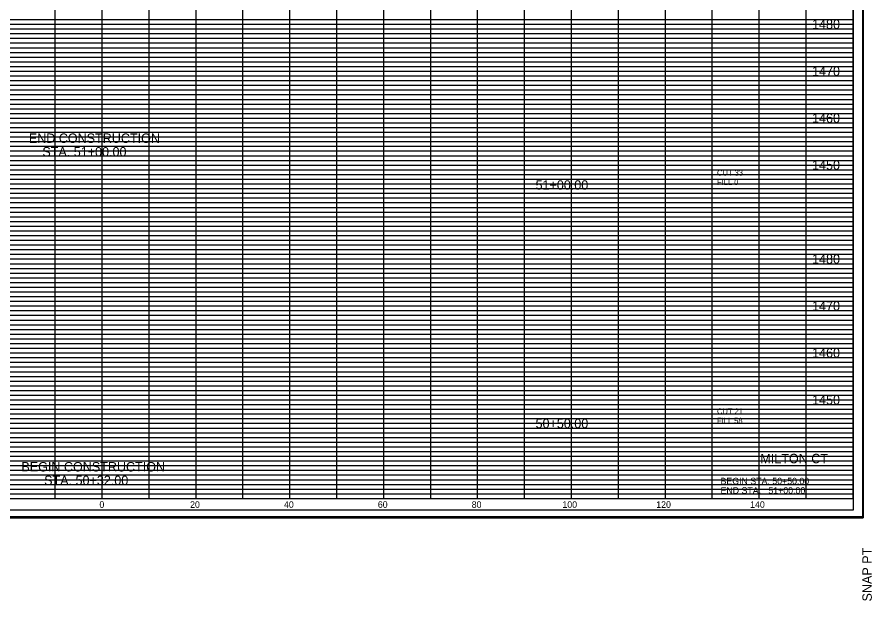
# Model space of a CAD drawing. Extents: x 980 to 1324, y 978 to 1227.
# Drawn here: x 1141.9 to 1324, y 978.2 to 1102.5 of the extents above; entities that cross this region are included whole.
import ezdxf

# ---------------------------------------------------------------- set-up
doc = ezdxf.new("R2010")
doc.units = 0
for name, color, linetype in [('DESIGN - SHEET - Corner Text', 7, 'Continuous'), ('DESIGN - SHEET - Light Grid', 7, 'Continuous'), ('DESIGN - SHEET - Linework', 7, 'Continuous'), ('DESIGN - SHEET - Plot Shape', 7, 'Continuous'), ('DESIGN - TYPICAL - Finished Grade and Subgrade', 7, 'Continuous'), ('DESIGN - TYPICAL - Text', 7, 'Continuous')]:
    doc.layers.add(name, color=color, linetype=linetype)

# ---------------------------------------------------------------- blocks, each defined once
blk = doc.blocks.new('XSTSHT')
at = {"layer": 'DESIGN - SHEET - Light Grid'}
for p, q in [((8, 10.2), (16, 10.2)), ((16, 10.2), (24, 10.2)), ((24, 10.2), (32, 10.2)), ((8, 10.1), (16, 10.1)), ((16, 10.1), (24, 10.1)), ((24, 10.1), (32, 10.1)), ((8, 9.9), (16, 9.9)), ((16, 9.9), (24, 9.9)), ((24, 9.9), (32, 9.9)), ((8, 9.8), (16, 9.8)), ((8, 9.7), (16, 9.7)), ((16, 9.8), (24, 9.8)), ((16, 9.7), (24, 9.7)), ((24, 9.8), (32, 9.8)), ((24, 9.7), (32, 9.7)), ((8, 9.6), (16, 9.6)), ((8, 9.5), (16, 9.5)), ((16, 9.6), (24, 9.6)), ((16, 9.5), (24, 9.5)), ((24, 9.6), (32, 9.6)), ((24, 9.5), (32, 9.5)), ((8, 9.4), (16, 9.4)), ((8, 9.3), (16, 9.3)), ((16, 9.4), (24, 9.4)), ((16, 9.3), (24, 9.3)), ((24, 9.4), (32, 9.4)), ((24, 9.3), (32, 9.3)), ((8, 9.2), (16, 9.2)), ((16, 9.2), (24, 9.2)), ((24, 9.2), (32, 9.2)), ((8, 9.1), (16, 9.1)), ((16, 9.1), (24, 9.1)), ((24, 9.1), (32, 9.1)), ((8, 8.9), (16, 8.9)), ((8, 8.8), (16, 8.8)), ((16, 8.9), (24, 8.9)), ((16, 8.8), (24, 8.8)), ((24, 8.9), (32, 8.9)), ((24, 8.8), (32, 8.8)), ((8, 8.7), (16, 8.7)), ((8, 8.6), (16, 8.6)), ((16, 8.7), (24, 8.7)), ((16, 8.6), (24, 8.6)), ((24, 8.7), (32, 8.7)), ((24, 8.6), (32, 8.6)), ((8, 8.5), (16, 8.5)), ((8, 8.4), (16, 8.4)), ((16, 8.5), (24, 8.5)), ((16, 8.4), (24, 8.4)), ((24, 8.5), (32, 8.5)), ((24, 8.4), (32, 8.4)), ((8, 8.3), (16, 8.3)), ((8, 8.2), (16, 8.2)), ((16, 8.3), (24, 8.3)), ((16, 8.2), (24, 8.2)), ((24, 8.3), (32, 8.3)), ((24, 8.2), (32, 8.2)), ((8, 8.1), (16, 8.1)), ((16, 8.1), (24, 8.1)), ((24, 8.1), (32, 8.1)), ((8, 7.9), (16, 7.9)), ((16, 7.9), (24, 7.9)), ((24, 7.9), (32, 7.9)), ((8, 7.8), (16, 7.8)), ((8, 7.7), (16, 7.7)), ((16, 7.8), (24, 7.8)), ((16, 7.7), (24, 7.7)), ((24, 7.8), (32, 7.8)), ((24, 7.7), (32, 7.7)), ((8, 7.6), (16, 7.6)), ((8, 7.5), (16, 7.5)), ((16, 7.6), (24, 7.6)), ((16, 7.5), (24, 7.5)), ((24, 7.6), (32, 7.6)), ((24, 7.5), (32, 7.5)), ((8, 7.4), (16, 7.4)), ((8, 7.3), (16, 7.3)), ((16, 7.4), (24, 7.4)), ((16, 7.3), (24, 7.3)), ((24, 7.4), (32, 7.4)), ((24, 7.3), (32, 7.3)), ((8, 7.2), (16, 7.2)), ((16, 7.2), (24, 7.2)), ((24, 7.2), (32, 7.2)), ((8, 7.1), (16, 7.1)), ((16, 7.1), (24, 7.1)), ((24, 7.1), (32, 7.1)), ((8, 6.9), (16, 6.9)), ((8, 6.8), (16, 6.8)), ((16, 6.9), (24, 6.9)), ((16, 6.8), (24, 6.8)), ((24, 6.9), (32, 6.9)), ((24, 6.8), (32, 6.8)), ((8, 6.7), (16, 6.7)), ((8, 6.6), (16, 6.6)), ((16, 6.7), (24, 6.7)), ((16, 6.6), (24, 6.6)), ((24, 6.7), (32, 6.7)), ((24, 6.6), (32, 6.6)), ((8, 6.5), (16, 6.5)), ((8, 6.4), (16, 6.4)), ((16, 6.5), (24, 6.5)), ((16, 6.4), (24, 6.4)), ((24, 6.5), (32, 6.5)), ((24, 6.4), (32, 6.4)), ((8, 6.3), (16, 6.3)), ((8, 6.2), (16, 6.2)), ((16, 6.3), (24, 6.3)), ((16, 6.2), (24, 6.2)), ((24, 6.3), (32, 6.3)), ((24, 6.2), (32, 6.2)), ((8, 6.1), (16, 6.1)), ((16, 6.1), (24, 6.1)), ((24, 6.1), (32, 6.1)), ((8, 5.9), (16, 5.9)), ((16, 5.9), (24, 5.9)), ((24, 5.9), (32, 5.9)), ((8, 5.8), (16, 5.8)), ((8, 5.7), (16, 5.7)), ((16, 5.8), (24, 5.8)), ((16, 5.7), (24, 5.7)), ((24, 5.8), (32, 5.8)), ((24, 5.7), (32, 5.7)), ((8, 5.6), (16, 5.6)), ((8, 5.5), (16, 5.5)), ((16, 5.6), (24, 5.6)), ((16, 5.5), (24, 5.5)), ((24, 5.6), (32, 5.6)), ((24, 5.5), (32, 5.5)), ((8, 5.4), (16, 5.4)), ((8, 5.3), (16, 5.3)), ((16, 5.4), (24, 5.4)), ((16, 5.3), (24, 5.3)), ((24, 5.4), (32, 5.4)), ((24, 5.3), (32, 5.3)), ((8, 5.2), (16, 5.2)), ((8, 5.1), (16, 5.1)), ((16, 5.2), (24, 5.2)), ((16, 5.1), (24, 5.1)), ((24, 5.2), (32, 5.2)), ((24, 5.1), (32, 5.1)), ((8, 4.9), (16, 4.9)), ((8, 4.8), (16, 4.8)), ((16, 4.9), (24, 4.9)), ((16, 4.8), (24, 4.8)), ((24, 4.9), (32, 4.9)), ((24, 4.8), (32, 4.8)), ((8, 4.7), (16, 4.7)), ((8, 4.6), (16, 4.6)), ((16, 4.7), (24, 4.7)), ((16, 4.6), (24, 4.6)), ((24, 4.7), (32, 4.7)), ((24, 4.6), (32, 4.6)), ((8, 4.5), (16, 4.5)), ((8, 4.4), (16, 4.4)), ((16, 4.5), (24, 4.5)), ((16, 4.4), (24, 4.4)), ((24, 4.5), (32, 4.5)), ((24, 4.4), (32, 4.4)), ((8, 4.3), (16, 4.3)), ((8, 4.2), (16, 4.2)), ((16, 4.3), (24, 4.3)), ((16, 4.2), (24, 4.2)), ((24, 4.3), (32, 4.3)), ((24, 4.2), (32, 4.2)), ((8, 4.1), (16, 4.1)), ((16, 4.1), (24, 4.1)), ((24, 4.1), (32, 4.1)), ((8, 3.9), (16, 3.9)), ((16, 3.9), (24, 3.9)), ((24, 3.9), (32, 3.9)), ((8, 3.8), (16, 3.8)), ((8, 3.7), (16, 3.7)), ((16, 3.8), (24, 3.8)), ((16, 3.7), (24, 3.7)), ((24, 3.8), (32, 3.8)), ((24, 3.7), (32, 3.7)), ((8, 3.6), (16, 3.6)), ((8, 3.5), (16, 3.5)), ((16, 3.6), (24, 3.6)), ((16, 3.5), (24, 3.5)), ((24, 3.6), (32, 3.6)), ((24, 3.5), (32, 3.5)), ((8, 3.4), (16, 3.4)), ((8, 3.3), (16, 3.3)), ((16, 3.4), (24, 3.4)), ((16, 3.3), (24, 3.3)), ((24, 3.4), (32, 3.4)), ((24, 3.3), (32, 3.3)), ((8, 3.2), (16, 3.2)), ((8, 3.1), (16, 3.1)), ((16, 3.2), (24, 3.2)), ((16, 3.1), (24, 3.1)), ((24, 3.2), (32, 3.2)), ((24, 3.1), (32, 3.1)), ((8, 2.9), (16, 2.9)), ((8, 2.8), (16, 2.8)), ((16, 2.9), (24, 2.9)), ((16, 2.8), (24, 2.8)), ((24, 2.9), (32, 2.9)), ((24, 2.8), (32, 2.8)), ((8, 2.7), (16, 2.7)), ((8, 2.6), (16, 2.6)), ((16, 2.7), (24, 2.7)), ((16, 2.6), (24, 2.6)), ((24, 2.7), (32, 2.7)), ((24, 2.6), (32, 2.6)), ((8, 2.5), (16, 2.5)), ((8, 2.4), (16, 2.4)), ((16, 2.5), (24, 2.5)), ((16, 2.4), (24, 2.4)), ((24, 2.5), (32, 2.5)), ((24, 2.4), (32, 2.4)), ((8, 2.3), (16, 2.3)), ((8, 2.2), (16, 2.2)), ((16, 2.3), (24, 2.3)), ((16, 2.2), (24, 2.2)), ((24, 2.3), (32, 2.3)), ((24, 2.2), (32, 2.2)), ((8, 2.1), (16, 2.1)), ((16, 2.1), (24, 2.1)), ((24, 2.1), (32, 2.1)), ((8, 1.9), (16, 1.9)), ((16, 1.9), (24, 1.9)), ((24, 1.9), (32, 1.9)), ((8, 1.8), (16, 1.8)), ((8, 1.7), (16, 1.7)), ((16, 1.8), (24, 1.8)), ((16, 1.7), (24, 1.7)), ((24, 1.8), (32, 1.8)), ((24, 1.7), (32, 1.7)), ((8, 1.6), (16, 1.6)), ((8, 1.5), (16, 1.5)), ((16, 1.6), (24, 1.6)), ((16, 1.5), (24, 1.5)), ((24, 1.6), (32, 1.6)), ((24, 1.5), (32, 1.5)), ((8, 1.4), (16, 1.4)), ((8, 1.3), (16, 1.3)), ((16, 1.4), (24, 1.4)), ((16, 1.3), (24, 1.3)), ((24, 1.4), (32, 1.4)), ((24, 1.3), (32, 1.3)), ((8, 1.2), (16, 1.2)), ((8, 1.1), (16, 1.1)), ((16, 1.2), (24, 1.2)), ((16, 1.1), (24, 1.1)), ((24, 1.2), (32, 1.2)), ((24, 1.1), (32, 1.1)), ((8, 0.9), (16, 0.9)), ((8, 0.8), (16, 0.8)), ((16, 0.9), (24, 0.9)), ((16, 0.8), (24, 0.8)), ((24, 0.9), (32, 0.9)), ((24, 0.8), (32, 0.8)), ((8, 0.7), (16, 0.7)), ((8, 0.6), (16, 0.6)), ((16, 0.7), (24, 0.7)), ((16, 0.6), (24, 0.6)), ((24, 0.7), (32, 0.7)), ((24, 0.6), (32, 0.6)), ((8, 0.5), (16, 0.5)), ((8, 0.4), (16, 0.4)), ((16, 0.5), (24, 0.5)), ((16, 0.4), (24, 0.4)), ((24, 0.5), (32, 0.5)), ((24, 0.4), (32, 0.4)), ((8, 0.3), (16, 0.3)), ((8, 0.2), (16, 0.2)), ((16, 0.3), (24, 0.3)), ((16, 0.2), (24, 0.2)), ((24, 0.3), (32, 0.3)), ((24, 0.2), (32, 0.2)), ((8, 0.1), (16, 0.1)), ((16, 0.1), (24, 0.1)), ((24, 0.1), (32, 0.1))]:
    blk.add_line(p, q, dxfattribs=at)
at = {"layer": 'DESIGN - SHEET - Linework'}
for p, q in [((32.217, 21.414), (32.217, -0.414)), ((15, 0), (15, 21)), ((16, 0), (16, 21)), ((17, 0), (17, 21)), ((18, 0), (18, 21)), ((19, 0), (19, 21)), ((20, 0), (20, 21)), ((21, 0), (21, 21)), ((22, 0), (22, 21)), ((23, 0), (23, 21)), ((24, 0), (24, 21)), ((25, 0), (25, 21)), ((26, 0), (26, 21)), ((27, 0), (27, 21)), ((28, 0), (28, 20)), ((29, 0), (29, 20)), ((30, 0), (30, 20)), ((31, 0), (31, 20)), ((0, 10), (32, 10)), ((0, 9), (32, 9)), ((0, 8), (32, 8)), ((0, 7), (32, 7)), ((0, 6), (32, 6)), ((0, 5), (32, 5)), ((0, 4), (32, 4)), ((0, 3), (32, 3)), ((0, 2), (32, 2)), ((0, 1), (32, 1)), ((-1.823, -0.414), (32.217, -0.414))]:
    blk.add_line(p, q, dxfattribs=at)
blk.add_lwpolyline([(0, 21), (0, 0), (32, 0), (32, 21), (0, 21)], dxfattribs=at)
at = {"layer": 'DESIGN - SHEET - Plot Shape'}
for points in [[(-1.803, 21.394), (32.197, 21.394), (32.197, -0.394), (-1.803, -0.394)], [(-0.85, 21), (32, 21), (32, -0.25), (-0.85, -0.25)]]:
    blk.add_lwpolyline(points, close=True, dxfattribs=at)
at = {"layer": 'DESIGN - SHEET - Corner Text'}
blk.add_text('SNAP PT  ', height=0.2, rotation=90, dxfattribs=at).set_placement((32.397, -2.194))

msp = doc.modelspace()

# ---------------------------------------------------------------- block references
at = {"layer": 'DESIGN - TYPICAL - Finished Grade and Subgrade', "xscale": 10, "yscale": 10}
msp.add_blockref('XSTSHT', (1000, 1000), dxfattribs=at)

# ---------------------------------------------------------------- texts
at = {"layer": 'DESIGN - SHEET - Corner Text'}
for s, height, p in [('1480', 2, (1311.25, 1100)), ('1470', 2, (1311.25, 1090)), ('1460', 2, (1311.25, 1080)), ('1450', 2, (1311.25, 1070)), ('51+00.00', 2, (1252.34, 1065.76)), ('1480', 2, (1311.25, 1050)), ('1470', 2, (1311.25, 1040)), ('1460', 2, (1311.25, 1030)), ('1450', 2, (1311.25, 1020)), ('50+50.00', 2, (1252.34, 1014.97)), ('MILTON CT', 2, (1300.23, 1007.5)), ('BEGIN STA. 50+50.00', 1.4, (1291.75, 1003)), ('END STA.   51+00.00', 1.4, (1291.75, 1001)), ('0', 1.4, (1159.42, 998)), ('0', 1.4, (1159.42, 998)), ('20', 1.4, (1178.74, 998)), ('40', 1.4, (1198.74, 998)), ('60', 1.4, (1218.74, 998)), ('80', 1.4, (1238.74, 998)), ('100', 1.4, (1258.06, 998)), ('120', 1.4, (1278.06, 998)), ('140', 1.4, (1298.06, 998))]:
    msp.add_text(s, height=height, dxfattribs=at).set_placement(p)
at = {"layer": 'DESIGN - TYPICAL - Text'}
for s, height, p in [('END CONSTRUCTION', 2, (1144.38, 1075.73)), ('STA. 51+00.00', 2, (1147.27, 1072.83)), ('CUT 33', 1.2, (1291, 1068.76)), ('FILL 0', 1.2, (1291, 1066.76)), ('CUT 21', 1.2, (1291, 1017.97)), ('FILL 58', 1.2, (1291, 1015.97)), ('BEGIN CONSTRUCTION', 2, (1142.8, 1005.75)), ('STA. 50+32.00', 2, (1147.65, 1002.85))]:
    msp.add_text(s, height=height, dxfattribs=at).set_placement(p)

doc.saveas('drawing.dxf')
